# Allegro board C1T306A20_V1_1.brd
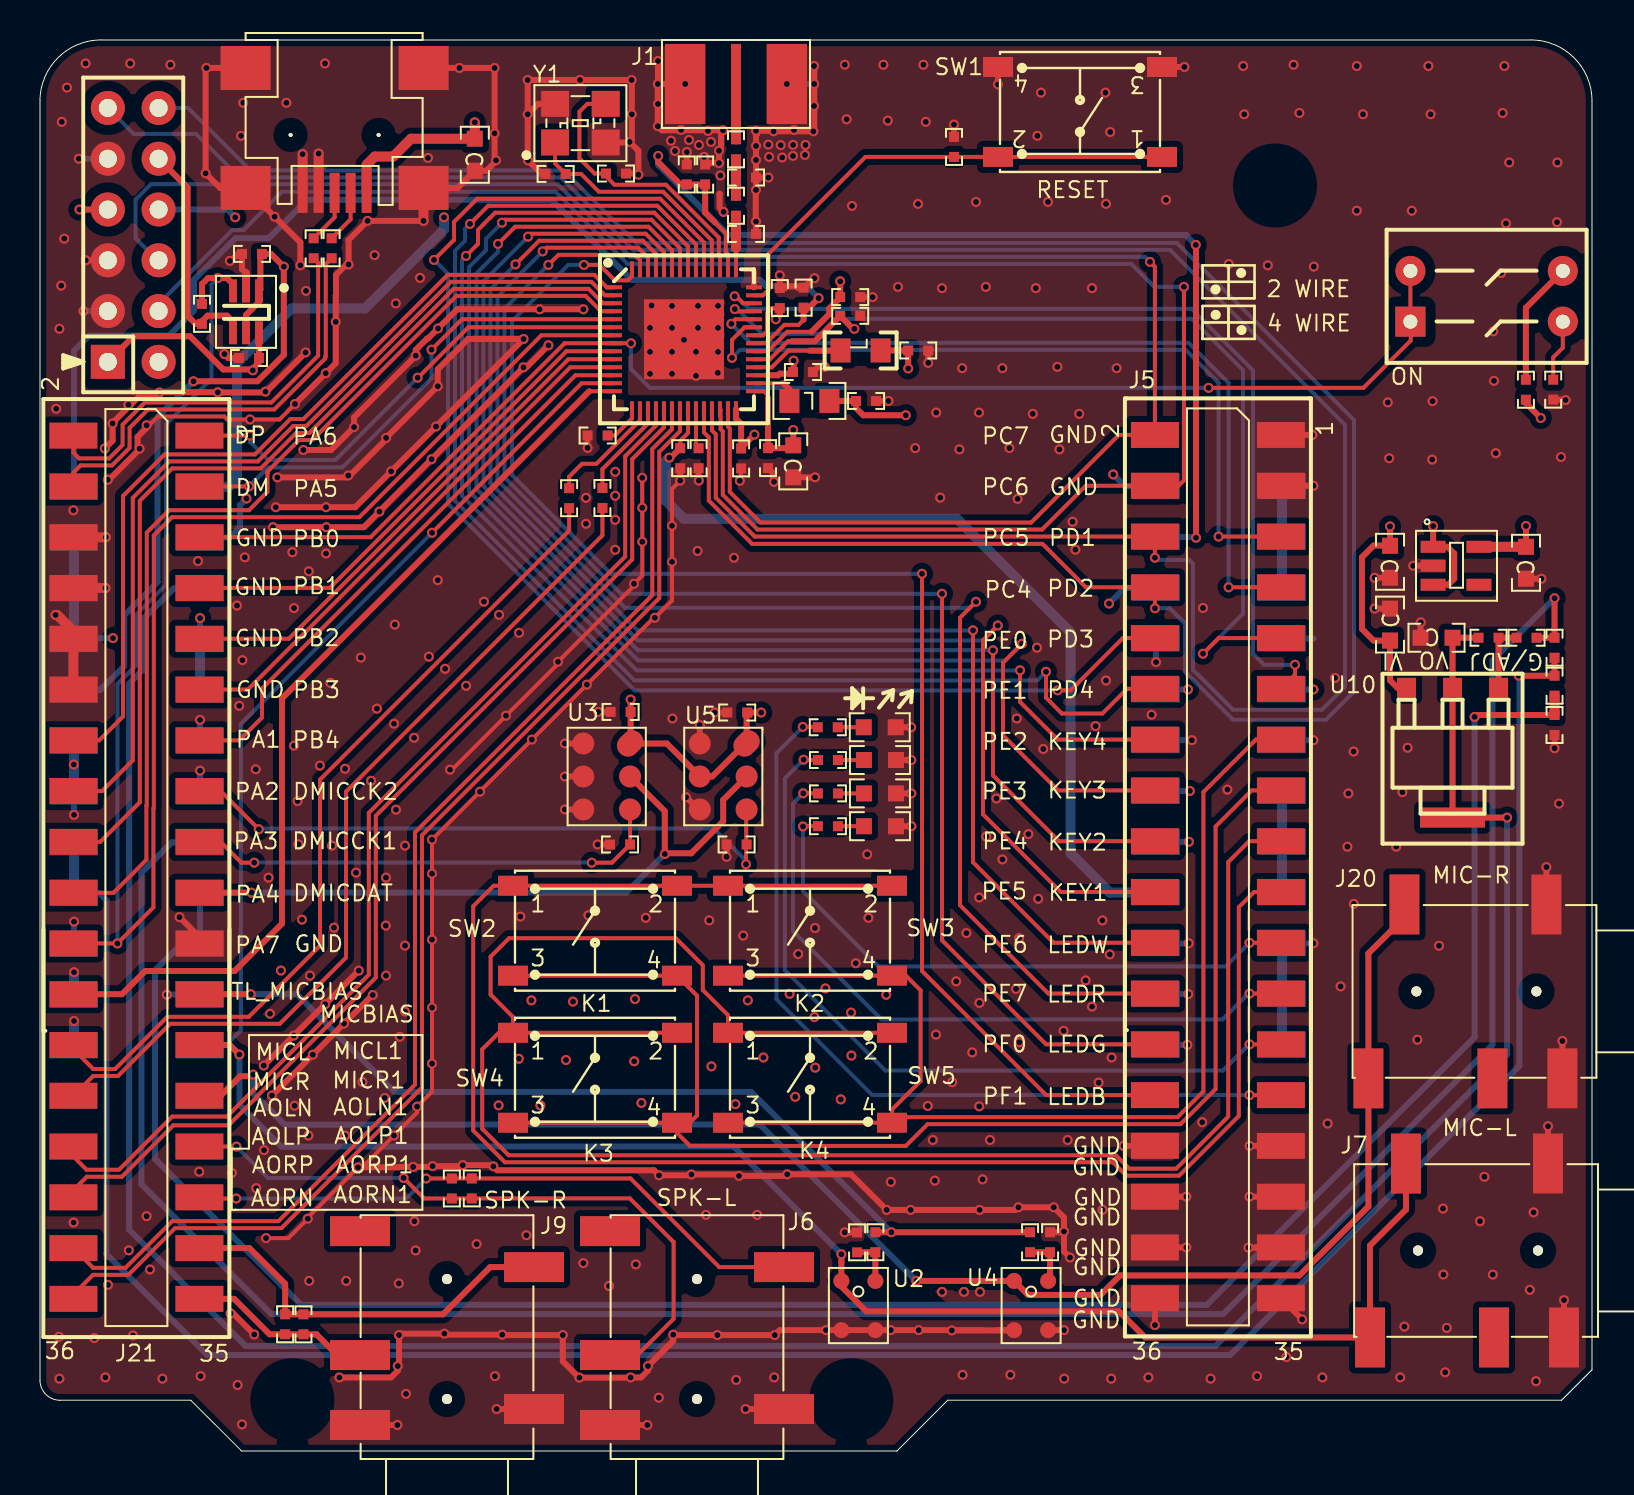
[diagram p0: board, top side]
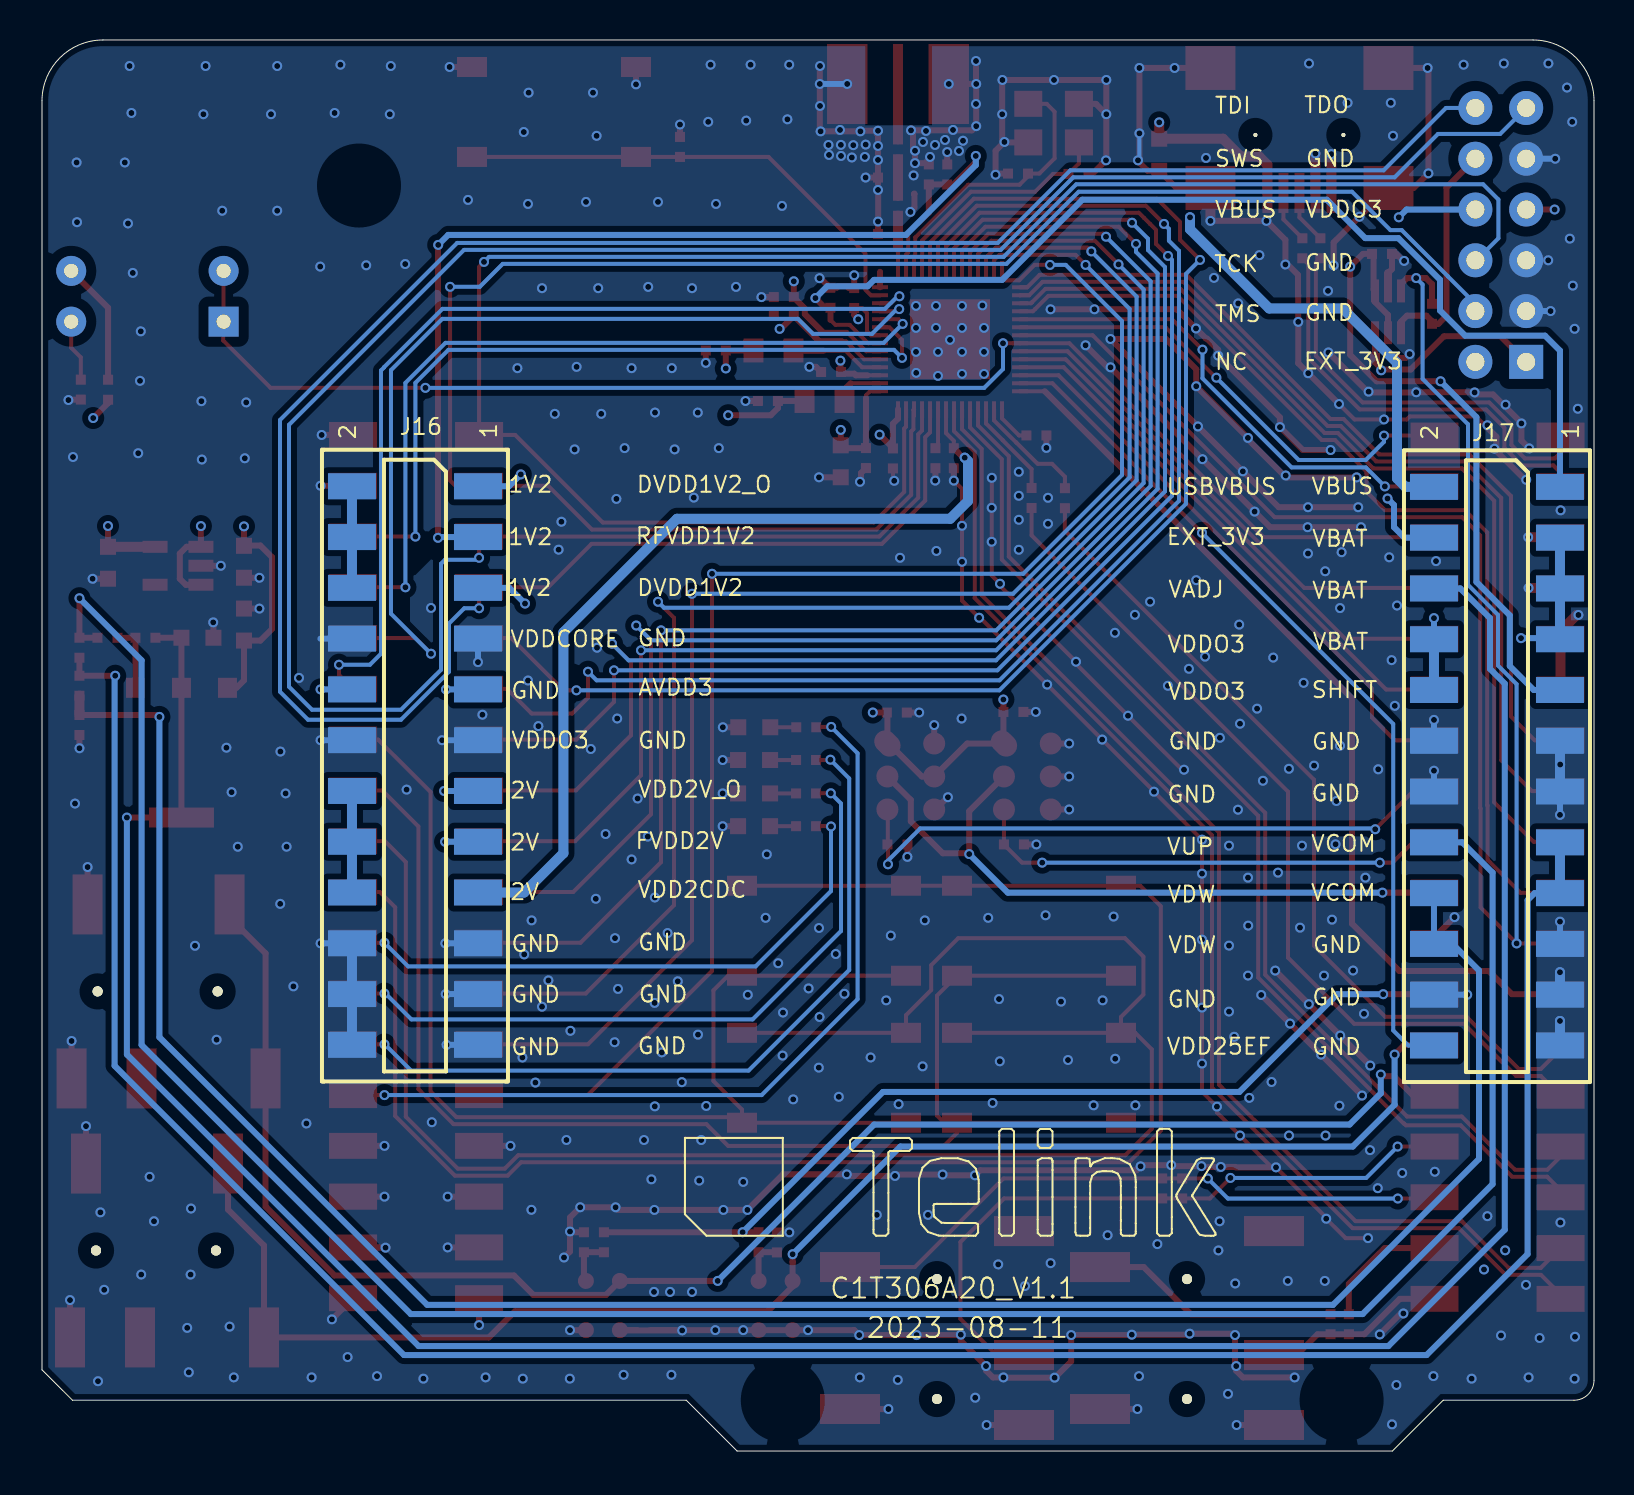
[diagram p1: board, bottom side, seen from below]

Outline 77.6 x 70.58 mm; copper layers: TOP, GND, POWER, BOTTOM. Coordinates in mm from the lower left corner of the outline.
Outline path: 0,67.53 arc(0.89,69.69) 3.05,70.58 74.55,70.58 arc(76.71,69.69) 77.6,67.53 77.6,4.06 76.08,2.54 45.39,2.54 42.85,0 10.08,0 7.54,2.54 1,2.54 arc(0.29,2.83) 0,3.54 0,67.53

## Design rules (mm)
constraint set DEFAULT: min track width 0.15

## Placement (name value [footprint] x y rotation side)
C1  NC  [0402]  28.8 63.9 180 top
C2  NC  [0402]  25.78 63.88 0 top
C3  0.1uF  [0402]  33.26 63.85 90 top
C4  2.2uF  [0402]  32.34 63.85 90 top
C5  1.5pF  [0402]  35.3 60.88 180 top
C6  1.2pF  [0402]  35.3 63.7 180 top
C9  1uF  [0402]  45.7 65.23 90 top
C10  1uF  [0402]  36.99 57.67 90 top
C11  1uF  [0402]  38.18 57.69 90 top
C12  1uF  [0402]  40.51 56.78 0 top
C13  1uF  [0402]  40.51 57.72 0 top
C14  1uF  [0402]  43.91 55.05 0 top
C15  1uF  [0402]  27.88 50.8 0 top
C16  1uF  [0402]  35.06 49.65 270 top
C17  1uF  [0402]  38.15 53.97 0 top
C18  1uF  [0402]  36.4 49.67 270 top
C19  1uF  [0402]  26.46 47.66 90 top
C20  1uF  [0402]  28.12 47.67 90 top
C21  1uF  [0402]  41.3 52.52 0 top
C22  1uF  [0402]  32.01 49.66 270 top
C23  1uF  [0402]  32.93 49.66 270 top
C25  NC  [0402]  21.59 13.13 90 top
C26  1uF  [0402]  40.85 10.44 90 top
C27  0.1uF  [0402]  34.86 36.94 180 top
C28  NC  [0402]  13.17 6.34 90 top
C29  1uF  [0402]  50.5 10.44 90 top
C30  10uF  [0603C]  21.74 64.84 270 top
C31  0.1uF  [0402]  29.03 36.97 180 top
C33  0.1uF  [0402]  10.6 59.88 180 top
C34  0.1uF  [0402]  10.45 54.67 180 top
C37  10uF  [0603C]  67.5 41.34 90 top
C38  10uF  [0603C]  67.5 44.48 270 top
C39  10uF  [0603C]  74.3 44.43 270 top
C40  10uF  [0603C]  69.83 40.68 180 top
C43  10uF  [0603C]  37.66 49.5 270 top
D1  Blue  [0603-LED]  41.99 36.2 0 top
D2  Green  [0603-LED]  42 34.56 0 top
D3  White  [0603-LED]  42 31.25 0 top
D4  Red  [0603-LED]  42 32.89 0 top
J1  RFIN  [SMA-H]  34.8 68.38 270 top
J5  HEADER 18X2  [SMD254M-2X18_RX1_30Y2_40]  58.9 24.15 90 top
J6  AOPHR  [PJ-327]  32.85 -0.4 180 top
J7  AIL1  [PJ-327]  77.9 10.03 270 top
J9  AOPHR  [PJ-327]  20.35 -0.4 180 top
J11  USB_MiniABF  [USB-MINI-F5]  14.73 62.93 180 top
J12  DIP_2X2  [DIPSWITCH_2P54_7P62_2X2]  72.33 57.76 270 top
J15  JTAG  [HDR254F-2X6X850]  3.39 67.18 270 top
J16  HEADER 12X2  [SMD254M-2X12_RX1_30Y2_40]  58.95 34.29 90 bottom
J17  HEADER 12X2  [SMD254M-2X12_RX1_30Y2_40]  4.85 34.26 90 bottom
J20  AIL1  [PJ-327]  77.82 22.99 270 top
J21  HEADER 18X2  [SMD254M-2X18_RX1_30Y2_40]  4.82 24.12 90 top
L1  3nH  [0402]  34.8 62.29 90 top
L2  2.2uH  [0805L]  41.03 55.05 0 top
L3  2.2uH  [0805L]  38.47 52.53 0 top
L4  1.5nH  [0402]  34.8 65.11 90 top
R4  1K  [0402]  39.39 36.2 0 top
R5  1K  [0402]  39.4 34.56 0 top
R6  1K  [0402]  39.4 31.25 0 top
R7  1K  [0402]  39.4 32.89 0 top
R8  NC  [0402]  20.59 13.13 90 top
R9  2.2K  [0402]  41.77 10.44 270 top
R10  100K  [0402]  29 30.34 0 top
R11  NC  [0402]  12.26 6.34 90 top
R12  2.2K  [0402]  49.5 10.44 270 top
R13  100K  [0402]  34.83 30.34 0 top
R14  33  [0402R]  14.58 60.16 270 top
R15  33  [0402R]  13.68 60.16 270 top
R16  1K  [0402]  74.3 53.09 90 top
R17  1M  [0402]  75.66 53.09 90 top
R26  0R  [0402R]  8.1 56.88 270 top
R33  430R  [0402]  74.33 40.68 0 top
R34  1.15K  [0402]  75.73 40.18 270 top
R35  787R  [0402]  75.73 38.28 270 top
R36  464R  [0402]  75.73 36.32 270 top
R37  1K  [0402]  72.43 40.68 180 top
SW1  SW4PIN_4.5x4.5  [SW_6X6_SMD]  52 66.98 180 top
SW2  SW4PIN_4.5x4.5  [SW_6X6_SMD]  27.75 26.03 0 top
SW3  SW4PIN_4.5x4.5  [SW_6X6_SMD]  38.5 26.03 0 top
SW4  SW4PIN_4.5x4.5  [SW_6X6_SMD]  27.75 18.67 0 top
SW5  SW4PIN_4.5x4.5  [SW_6X6_SMD]  38.5 18.67 0 top
U1  TLSR9527C  [QFN_7X7_56PIN_0P4_5P20X5P20]  32.2 55.61 0 top
U2  WMM7037AT2  [GA_BFA423_A83]  40.92 7.28 0 top
U3  WMM7047DTFN0  [DMIC_SPM0423HM4H-WB]  28.33 33.74 270 top
U4  WMM7037AT2  [GA_BFA423_A83]  49.55 7.28 0 top
U5  WMM7047DTFN0  [DMIC_SPM0423HM4H-WB]  34.16 33.74 270 top
U8  NC/TXS0101  [SC70-6]  10.3 56.98 180 top
U10  LM1117-ADJ  [SOT-223]  70.63 34.68 180 top
U11  CE1132-33M  [SOT-23-5]  70.8 44.28 270 top
Y1  24MHz-12pF-+/-10ppm  [OSCCC250X320X110]  27.02 66.42 90 top

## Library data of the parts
C1 C2 = C1005_NC
C3 C4 C9-C18 C21-C23 C26 C27 C29 C31 C38 C39 = C1005X5R1C104K
C5 C6 = C1608_NC
C19 C20 C25 C28 = C1005X5R1C105K
C30 C37 = C1608X5R0J106M
C33 C34 C40 = C1608X5R1C105M
C43 = C1005X5R1C104K_0
D1-D4 = 0603D_Green
J1 = SMA_JACK_2
J5 J21 = HEADER 18X2: Tolerance: RichardLC
J6 J7 J9 J20 = PJ327_2
J11 = USB_MiniABF_5pin: User Part Number: pn; Tolerance: RichardLC
J12 = HEADER 2X2_0: User Part Number: pn; Tolerance: RichardLC
J15 = HEADER 6X2: User Part Number: pn; Tolerance: RichardLC
J16 J17 = HEADER 12X2: Tolerance: RichardLC
L1 L4 = MLK1608_000R
L2 L3 = IND
R4-R7 = RS0402K102JT
R8-R13 R16 R17 = RS0402K104JT
R14 R15 = RS0603K330JT
R26 = RS0603K102JT
R33-R37 = RS0603K104JT
SW1-SW5 = SW_6X6_SMD_0
U1 = TLSR9527C: Tolerance: RichardLC
U2 U4 = MULPS4CX-RM5_0
U3 U5 = LD1117/SO_0
U8 = TXS0101
U10 = XC62FP3302_0.3V_SOT-89
U11 = XC6219_6.3V_SOT-23-5
Y1 = CRYSTAL4/SM_0: Tolerance: RichardLC

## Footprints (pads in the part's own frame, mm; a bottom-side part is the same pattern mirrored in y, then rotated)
0402
  rect 0.5x0.5 smd: 1(-0.5,0) 2(0.5,0)
0402R
  rect 0.5x0.5 smd: 1(-0.5,0) 2(0.5,0)
0603-LED
  rect 0.8x0.8 smd: A(-0.8,0) C(0.8,0)
0603C
  rect 0.8x0.8 smd: 1(-0.8,0) 2(0.8,0)
0805L
  rect 1x1.2 smd: 1(-1,0) 2(1,0)
DIPSWITCH_2P54_7P62_2X2
  rect 1.5x1.5 hole 0.7: 1(1.27,-3.81)
  round 1.5 hole 0.7: 2(1.27,3.81) 3(-1.27,-3.81) 4(-1.27,3.81)
DMIC_SPM0423HM4H-WB
  round 1.1 smd: 1(-1.65,-1.17) 2(0,-1.17) 3(1.65,-1.17) 4(1.65,1.17) 5(0,1.17)
  oval 1.4x1.1 smd rot 135: 6(-1.65,1.17)
GA_BFA423_A83
  round 0.8 smd: 1(-0.85,1.23) 2(-0.85,-1.23) 3(0.85,-1.23) 4(0.85,1.23)
HDR254F-2X6X850
  rect 1.7x1.7 hole 0.9: 1(12.7,0)
  round 1.7 hole 0.9: 2(12.7,2.54) 3(10.16,0) 4(10.16,2.54) 5(7.62,0) 6(7.62,2.54) 7(5.08,0) 8(5.08,2.54) 9(2.54,0) 10(2.54,2.54) 11(0,0) 12(0,2.54)
OSCCC250X320X110
  rect 1.3x1.4 smd: 1(-0.965,1.265) 2(-0.965,-1.265) 3(0.965,-1.265) 4(0.965,1.265)
PJ-327
  round 0.5 hole 1: (0,-3) (0,-9)
  rect 3x1.5 smd: 1(-4.35,-2.5) 2(4.35,-5.2) 3(-4.35,-9.6) 4(4.35,-11.4) 5(4.35,-1.7)
QFN_7X7_56PIN_0P4_5P20X5P20
  rect 0.8x0.2 smd: 1(-3.5,2.6) 2(-3.5,2.2) 3(-3.5,1.8) 4(-3.5,1.4) 5(-3.5,1) 6(-3.5,0.6) 7(-3.5,0.2) 8(-3.5,-0.2) 9(-3.5,-0.6) 10(-3.5,-1) 11(-3.5,-1.4) 12(-3.5,-1.8) 13(-3.5,-2.2) 14(-3.5,-2.6) 29(3.5,-2.6) 30(3.5,-2.2) 31(3.5,-1.8) 32(3.5,-1.4) 33(3.5,-1) 34(3.5,-0.6) 35(3.5,-0.2) 36(3.5,0.2) 37(3.5,0.6) 38(3.5,1) 39(3.5,1.4) 40(3.5,1.8) 41(3.5,2.2) 42(3.5,2.6)
  rect 0.2x0.8 smd: 15(-2.6,-3.5) 16(-2.2,-3.5) 17(-1.8,-3.5) 18(-1.4,-3.5) 19(-1,-3.5) 20(-0.6,-3.5) 21(-0.2,-3.5) 22(0.2,-3.5) 23(0.6,-3.5) 24(1,-3.5) 25(1.4,-3.5) 26(1.8,-3.5) 27(2.2,-3.5) 28(2.6,-3.5) 43(2.6,3.5) 44(2.2,3.5) 45(1.8,3.5) 46(1.4,3.5) 47(1,3.5) 48(0.6,3.5) 49(0.2,3.5) 50(-0.2,3.5) 51(-0.6,3.5) 52(-1,3.5) 53(-1.4,3.5) 54(-1.8,3.5) 55(-2.2,3.5) 56(-2.6,3.5)
  rect 4x4 smd: 57(0,0)
SC70-6
  rect 0.4x1.15 smd: 1(-0.65,-1.045) 2(0,-1.045) 3(0.65,-1.045) 4(0.65,1.045) 5(0,1.045) 6(-0.65,1.045)
SMA-H
  rect 4x0.5 smd: 1(0,0)
  rect 4x2 smd: 2(0,-2.54) 3(0,2.54) 4(0,-2.54) 5(0,2.54)
SMD254M-2X12_RX1_30Y2_40
  rect 1.3x2.4 smd: 1(13.97,-3.15) 2(13.97,3.15) 3(11.43,-3.15) 4(11.43,3.15) 5(8.89,-3.15) 6(8.89,3.15) 7(6.35,-3.15) 8(6.35,3.15) 9(3.81,-3.15) 10(3.81,3.15) 11(1.27,-3.15) 12(1.27,3.15) 13(-1.27,-3.15) 14(-1.27,3.15) 15(-3.81,-3.15) 16(-3.81,3.15) 17(-6.35,-3.15) 18(-6.35,3.15) 19(-8.89,-3.15) 20(-8.89,3.15) 21(-11.43,-3.15) 22(-11.43,3.15) 23(-13.97,-3.15) 24(-13.97,3.15)
SMD254M-2X18_RX1_30Y2_40
  rect 1.3x2.4 smd: 1(26.67,-3.15) 2(26.67,3.15) 3(24.13,-3.15) 4(24.13,3.15) 5(21.59,-3.15) 6(21.59,3.15) 7(19.05,-3.15) 8(19.05,3.15) 9(16.51,-3.15) 10(16.51,3.15) 11(13.97,-3.15) 12(13.97,3.15) 13(11.43,-3.15) 14(11.43,3.15) 15(8.89,-3.15) 16(8.89,3.15) 17(6.35,-3.15) 18(6.35,3.15) 19(3.81,-3.15) 20(3.81,3.15) 21(1.27,-3.15) 22(1.27,3.15) 23(-1.27,-3.15) 24(-1.27,3.15) 25(-3.81,-3.15) 26(-3.81,3.15) 27(-6.35,-3.15) 28(-6.35,3.15) 29(-8.89,-3.15) 30(-8.89,3.15) 31(-11.43,-3.15) 32(-11.43,3.15) 33(-13.97,-3.15) 34(-13.97,3.15) 35(-16.51,-3.15) 36(-16.51,3.15)
SOT-23-5
  rect 0.6x1.25 smd: 1(-0.95,-1.145) 2(0,-1.145) 3(0.95,-1.145) 4(0.95,1.145) 5(-0.95,1.145)
SOT-223
  rect 0.95x1 smd: 1(-2.3,-3.495) 2(0,-3.495) 3(2.3,-3.495)
  rect 3.25x1 smd: 4(0,2.995)
SW_6X6_SMD
  rect 1.5x1 smd: 1(-4.1,2.25) 2(4.1,2.25) 3(-4.1,-2.25) 4(4.1,-2.25)
USB-MINI-F5
  round 0.2 hole 0.9 unplated: (-2.2,-2.9) (2.2,-2.9)
  rect 0.5x2 smd: 1(-1.6,0) 2(-0.8,0) 3(0,0) 4(0.8,0) 5(1.6,0)
  rect 2.5x2.2 smd: 6(-4.45,-6.25) 7(4.45,-6.25) 8(-4.45,-0.25) 9(4.45,-0.25)

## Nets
GND: C1.1 C2.1 C3.2 C4.2 C5.1 C6.1 C9.2 C10.2 C11.2 C12.2 C13.2 C14.2 C15.1 C16.2 C17.2 C18.2 C21.2 C22.2 C23.2 C26.2 C27.2 C29.2 C30.2 C31.2 C33.2 C34.2 C37.2 C38.2 C39.2 C40.2 C43.2 D1.C(CATHODE) D2.C(CATHODE) D3.C(CATHODE) D4.C(CATHODE) J1.2 J1.3 J1.4 J1.5 J5.1 J5.3 J5.29 J5.30 J5.31 J5.32 J5.33 J5.34 J5.35 J5.36 J6.1 J6.5 J7.1 J7.5 J9.1 J9.5 J11.4 J11.5 J11.6 J11.7 J11.8 J11.9 J15.3 J15.5 J15.9 J16.7 J16.8 J16.11 J16.12 J16.19 J16.20 J16.21 J16.22 J16.23 J16.24 J17.11 J17.12 J17.13 J17.14 J17.19 J17.21 J17.22 J17.23 J20.1 J20.5 J21.6 J21.8 J21.10 J21.12 J21.21 R10.1 R13.1 R17.1 R36.2 SW1.3 SW1.4 U1.42 U1.57 U2.2 U2.3 U3.1 U3.2(SE) U3.3 U4.2 U4.3 U5.1 U5.3 U8.2 U11.2(VSS) Y1.2 Y1.4
VBAT_ADJ: C40.1 J17.6 R37.2 U10.2 U10.4(VOUT#4)
VBUS: C30.1 C37.1 C38.1 J11.1(V_BUS) J15.8 J17.2 U10.3 U11.1 U11.3
VDD25_EF: J17.24 U1.13
AOLN: C25.1 J6.2 J21.29 R8.1
AOLP: C25.2 J6.3 J21.31 R8.2
AORN: C28.1 J9.2 J21.35 R11.1
AORP: C28.2 J9.3 J21.33 R11.2
BEVK_SWS: J15.10 R26.2 U8.4
DM: J21.4 R14.2
DMICCK1: J21.17 R10.2 U3.4
DMICCK2: J21.15 R13.2 U5.4
DMICDAT: J21.19 U3.5 U5.5
DP: J21.2 R15.2
EXT_3V3: C34.1 C39.1 J15.1 J17.4 U8.6(VCCB) U11.5
LED_B: J5.27 R4.1
LED_G: J5.25 R5.1
LED_R: J5.23 R7.1
LED_W: J5.21 R6.1
LEVEL_SHIFT: C27.1 C31.1 C33.1 J17.9 U3.6 U5.2(SE) U5.6 U8.1 U8.5
MICBIAS: J21.23 R9.1 R12.1
MICL: J7.3 J7.4 J21.25 U2.1
MICR: J20.3 J20.4 J21.27 U4.1
TL_AOLN: J21.30 U1.18
TL_AOLP: J21.32 U1.19
TL_AORN: J21.36 U1.21
TL_AORP: J21.34 U1.20
TL_AVDD3: C10.1 J16.9 U1.36
TL_DVDD1V2: C17.1 J16.5 U1.31
TL_FVDD2V: C12.1 J16.15 U1.33
TL_KEY1: J5.19 SW2.1 SW2.2 SW3.1 SW3.2
TL_KEY2: J5.17 SW4.1 SW4.2 SW5.1 SW5.2
TL_KEY3: J5.15 SW2.3 SW2.4 SW4.3 SW4.4
TL_KEY4: J5.13 SW3.3 SW3.4 SW5.3 SW5.4
TL_MICBIAS: J21.24 U1.14
TL_MICL: C19.1 J21.26
TL_MICR: C20.1 J21.28
TL_PA1: J21.14 U1.1
TL_PA2: J21.16 U1.2
TL_PA3: J21.18 U1.3
TL_PA4: J21.20 U1.4
TL_PA5_DM: J21.3 U1.5
TL_PA6_DP: J21.1 U1.6
TL_PA7_SWS: J21.22 R26.1 U1.7 U8.3
TL_PB0: J12.1 J12.3 J21.5 U1.8
TL_PB1: J21.7 U1.9
TL_PB2: J21.9 U1.10
TL_PB3: J21.11 U1.11
TL_PB4: J21.13 U1.12
TL_PC4_TDI: J5.8 J15.12 U1.24
TL_PC5_TDO: J5.6 J15.11 U1.25
TL_PC6_TMS: J5.4 J15.4 U1.26
TL_PC7_TCK: J5.2 J15.6 U1.27
TL_PD1: J5.5 U1.37
TL_PD2: J5.7 U1.38
TL_PD3: J5.9 U1.39
TL_PD4: J5.11 U1.40
TL_PE0: J5.10 U1.47
TL_PE1: J5.12 U1.48
TL_PE2: J5.14 U1.49
TL_PE3: J5.16 U1.50
TL_PE4: J5.18 U1.51
TL_PE5: J5.20 U1.52
TL_PE6: J5.22 U1.53
TL_PE7: J5.24 U1.54
TL_PF0: J5.26 U1.55
TL_PF1: J5.28 U1.56
TL_RFVDD1V2: C3.1 C4.1 J16.3 U1.44
TL_RST: C9.1 SW1.1 SW1.2 U1.41
TL_VBAT: C18.1 C43.1 J17.3 J17.5 J17.7 U1.29
TL_VBUS: C11.1 J17.1 U1.35
TL_VDD1V2_O: C21.1 J16.1 L3.2
TL_VDD2CDC: C22.1 J16.17 U1.22
TL_VDD2V_O: C14.1 J16.13 L2.2
TL_VDDO3: C16.1 J15.7 J16.10 J17.8 J17.10 R16.1 U1.28
TL_XC1: C1.2 U1.45 Y1.3
TL_XC2: C2.2 U1.46(XC2) Y1.1
VCOM: J17.15 J17.17 R34.2 R35.1
VDW: J17.18 J17.20 R35.2 R36.1
VUP: J17.16 R33.2 R34.1
N20028206: R33.1 R37.1 U10.1
N20031302: L3.1 U1.30
N20031350: L2.1 U1.32
N20031395: C13.1 U1.34
N20031514: C5.2 L1.1 U1.43
N20031520: C6.2 L1.2 L4.1
N20031898: C23.1 U1.23
N20035363: C26.1 R9.2 U2.4(VDD)
N20035591: C29.1 R12.2 U4.4(VDD)
N20050417: J11.3 R15.1
N20050429: J11.2 R14.1
N20115519: J1.1 L4.2
N20131372: C15.2 U1.15
N20131385: C20.2 U1.17
N20131404: C19.2 U1.16
N20142968: J12.2 R17.2
N20142970: J12.4 R16.2
N20184397: J16.2 J16.4 J16.6
N20184465: J16.14 J16.16 J16.18
N200358921: D4.A R7.2
N200359000: D1.A R4.2
N200359081: D2.A R5.2
N200359160: D3.A R6.2

Pads without a net: J6 4; J7 2; J9 4; J15 2; J20 2; U11 4

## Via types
v1: diameter 0.5, hole 0.3, TOP to BOTTOM, 647 vias

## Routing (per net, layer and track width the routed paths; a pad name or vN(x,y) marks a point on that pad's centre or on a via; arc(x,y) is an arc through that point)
GND: length 451.7
  TOP w0.2: v1(12.75,52.37) 11.98,51.6 v1(10.5,51.6) 9.36,51.6 9.21,51.75 5.9,51.75 5.46,51.31 v1(5.33,51.31) ; v1(30.11,48.68) 30.11,47.18 v1(30.11,47.18) v1(30.11,45.48) 30.11,43.79 v1(29.7,43.38) 29.7,43.28 v1(25.9,39.48) 25.9,39.38 v1(23.3,36.78) 20.6,34.08 v1(20.5,34.08) ; v1(34.99,48.53) 34.99,48.42 35.05,48.48 35.05,49.06 35.1,49.11 C16.2 ; v1(11.3,10.65) 12.42,10.65 v1(13.39,11.62) 13.39,11.68 v1(15.9,14.19) ; v1(32.01,48.54) 31.6,48.13 v1(31.6,46.28) v1(31.6,44.48) 31.6,42.54 v1(30.74,41.68) 30.69,41.68 v1(27.34,38.34) v1(24.59,35.59) 22,32.99 v1(22,32.98) v1(19.6,30.58) 19.7,30.48 19.6,30.38 v1(19.6,28.88) v1(19.6,25.58) v1(19.6,22.18) v1(19.6,19.38) 19.6,17.97 v1(18.85,17.23) 18.85,16.93 v1(17.7,15.78) 16.11,14.19
  TOP w0.3: 45.58,6.05 v1(43.93,6.05) v1(42.54,6.05) U2.3 U2.2 v1(39.3,6.05) 36.99,6.05 v1(36.74,5.8) v1(33.87,5.8) 31.68,5.8 v1(31.66,5.82) 31.66,5.51 v1(30.4,4.25) 30.4,4.03 30.05,3.68 v1(29.53,3.68) 29.52,3.67 v1(26.97,3.67) 26.96,3.67 26.14,4.49 v1(26.14,5.8) 23.13,5.8 v1(23.11,5.82) 20.27,5.82 v1(20.22,5.87) 18.02,5.87 v1(17.95,5.8) 17.95,4.31 v1(17.89,4.25) 17.89,4.02 17.55,3.68 v1(14.97,3.68) ; 45.58,6.05 45.61,6.05 ; 45.58,6.05 v1(45.59,6.03) ; D4.C v1(43.57,32.89) ; 35.8,65.89 v1(35.8,65.28) v1(35.8,64.58) C6.1 ; 35.8,65.89 35.79,65.9 35.86,65.9 35.86,65.9 ; 35.8,65.89 v1(35.8,66.04) 36.65,66.04 v1(36.68,66.01) ; J5.35 v1(63.1,6.59) ; v1(11.19,19.28) v1(12.69,20.78) v1(14.26,22.35) v1(15.94,24.03) ; J5.32 v1(57.32,12.72) ; v1(11.87,48.7) 15.32,48.7 v1(15.42,48.8) 15.5,48.8 17.3,50.6 v1(17.3,50.68) v1(19.89,53.26) 19.89,54.11 21.4,55.62 v1(24.18,55.62) v1(19.8,51.25) v1(17.56,49) 15.76,47.21 v1(14.3,47.21) v1(11.79,47.21) ; J21.21 7.97,25.71 v1(6.97,26.7) ; v1(29.48,65.48) 29.59,65.59 v1(29.59,66.87) 29.59,68.57 v1(29.58,68.58) v1(27,68.58) v1(24.38,68.58) v1(24.38,66.87) ; v1(29.48,65.48) 29.92,65.04 v1(29.92,63.84) 29.83,63.84 29.77,63.9 C1.1 ; v1(29.48,65.48) 29.45,65.45 Y1.2 ; U4.3 v1(51.2,6.05) ; v1(3.39,48.58) 3.45,48.58 4.98,50.11 v1(4.98,50.14) 4.88,50.23 4.88,50.73 5.33,51.18 v1(5.33,51.31) ; C31.2 v1(27.91,36.97) ; C43.2 v1(38.75,48.7) ; J20.1 v1(75.32,29.21) ; v1(24.38,66.87) 24.38,64.68 24.4,64.66 v1(24.4,64.56) 24.58,64.38 24.58,64.38 25.08,63.88 C2.1 ; v1(24.38,66.87) 24.9,67.39 Y1.4 ; v1(69.04,41.45) 69.03,41.44 C40.2 ; C22.2 v1(32.01,48.54) ; v1(51.5,9.68) 51.2,9.98 v1(51.2,10.98) ; v1(16.64,22.81) 16.63,22.81 v1(15.2,21.38) v1(13.64,19.83) v1(11.6,17.78) ; J7.1 v1(75.4,16.25) ; v1(15.9,14.19) 17.93,14.19 17.95,14.21 v1(18.66,14.21) 19.59,14.21 v1(19.63,14.25) 21.09,14.25 v1(21.14,14.3) 22.61,14.3 v1(22.67,14.24) 22.87,14.04 30.7,14.04 v1(30.95,13.79) 32.53,13.79 v1(32.57,13.83) 34.88,13.83 v1(34.95,13.76) 37.28,13.76 v1(37.36,13.84) 40.55,13.84 v1(42.33,12.06) v1(43.53,12.06) v1(46.98,12.06) 48.79,12.06 v1(48.92,12.19) v1(50.69,12.19) 51.2,11.68 v1(51.2,10.98) ; C37.2 v1(66.73,42.14) ; J15.5 v1(2.29,59.56) ; C6.1 v1(36.42,63.7) ; C6.1 v1(35.8,63.08) 35.79,63.07 35.79,61.51 v1(35.8,61.5) C5.1 ; 45.61,6.05 v1(45.59,6.03) ; 45.61,6.05 47.17,6.05 ; v1(45.59,6.03) 48.69,6.03 U4.2 47.83,6.05 ; U11.2 v1(68.66,44.28) ; 33.98,62.9 34,62.88 33.98,62.86 33.98,62.2 34.18,62 v1(34.18,61.98) ; v1(36.68,66.01) 36.55,66.01 ; v1(36.68,66.01) v1(38.67,66.01) 38.71,66.05 v1(38.71,68.38) 38.71,69.27 v1(38.7,69.28) ; U3.3 v1(26.24,32.09) ; J5.1 v1(63.62,50.82) ; C29.2 51.16,10.94 v1(51.2,10.98) ; C26.2 v1(40.23,10.94) ; R36.2 v1(75.73,35.15) ; J5.36 v1(55.75,6.3) ; C18.2 36.65,48.92 36.65,48.53 v1(36.7,48.48) ; C3.2 33.32,64.42 v1(33.95,64.42) v1(33.95,65.04) 34.05,65.14 34.05,65.96 v1(34.15,66.06) 31.1,66.06 v1(30.89,66.27) v1(30.89,68.38) ; J5.34 v1(57.32,10.18) ; C17.2 38.9,54.23 v1(39.23,54.23) ; 10.3,58.92 10.1,59.12 C33.2 9.89,59.88 9.62,59.61 9.61,59.61 9.53,59.53 v1(9.49,59.53) ; v1(27.17,57.11) v1(24.98,57.11) 20.86,57.11 v1(19.9,56.15) 19.39,55.64 19.35,55.64 18.79,55.08 v1(18.79,54.79) 15.7,51.7 v1(15.7,51.22) 14.56,50.07 v1(13.17,50.07) ; J6.5 v1(30.37,1.3) ; J20.5 v1(76.12,20.51) ; J5.3 v1(63.67,48.28) ; v1(30.89,68.38) 30.9,68.39 v1(30.9,69.53) ; v1(30.89,68.38) v1(32.26,68.38) ; C21.2 v1(42.42,52.52) ; J5.30 v1(54.18,15.26) ; D1.C v1(43.56,36.2) ; J5.33 60.78,10.18 60.77,10.17 v1(60.42,10.17) ; R17.1 76.14,52.59 76.16,52.57 v1(76.28,52.57) ; v1(10.71,5.83) 9.66,6.88 v1(9.53,6.88) ; C27.2 v1(33.74,36.94) ; v1(12.75,52.37) v1(14.29,53.91) 14.79,54.41 v1(14.79,56.48) 14.79,57.8 14.8,57.81 14.8,58.83 15.32,59.35 v1(15.43,59.35) 15.43,60.58 v1(16.38,61.53) v1(19.18,61.53) 19.18,61.53 J11.8 20.88,63.18 C30.2 22.32,64.04 22.73,64.45 v1(22.73,65.91) v1(22.73,69.18) v1(20.97,69.18) J11.6 ; U5.1 v1(32.99,36.31) ; C9.2 v1(45.7,66.35) ; U1.42 35.7,58.98 ; U3.2 v1(26.24,33.74) ; v1(13.28,54.95) 11.32,52.99 v1(11.27,52.99) 11.23,52.95 9.1,52.95 9.09,52.96 v1(8.89,52.96) 5.98,52.96 v1(5.97,52.95) 5.87,52.85 5.05,52.85 4.54,52.34 v1(4.42,52.34) 4.42,52.22 3.73,51.53 3.73,51.5 v1(3.63,51.4) 3.63,50.54 v1(3.24,50.15) ; U5.3 32.93,32.09 32.32,32.7 v1(32.3,32.7) ; C13.2 v1(41.63,57.72) ; D2.C v1(43.57,34.56) ; R10.1 v1(27.88,30.34) ; J11.7 v1(8.32,69.18) 8.28,69.14 v1(8.28,63.91) 9.01,63.18 J11.9 11.72,61.74 v1(11.73,61.74) 13.02,60.45 v1(13.02,59.31) ; C39.2 v1(75.07,43.63) ; v1(32.94,48.54) 32.94,48.71 32.93,48.72 C23.2 ; D3.C v1(43.57,31.25) ; J5.29 v1(60.48,15.26) ; J6.1 v1(35.28,2.1) ; SW1.3 v1(57.22,69.23) ; v1(38.72,58.66) 38.67,58.66 38.2,58.19 C11.2 37.87,58.19 37.8,58.26 37.34,58.26 37.25,58.17 C10.2 v1(36.99,58.81) ; U3.1 v1(26.24,35.39) ; C14.2 v1(44.41,54.43) ; SW1.4 v1(47.9,68.36) ; v1(9.22,54.87) 9.42,54.67 C34.2 ; J7.5 v1(76.2,7.55) ; C38.2 v1(66.73,43.68) ; R13.1 v1(34.33,29.72) ; J9.1 v1(22.83,2.1) ; J5.31 v1(60.48,12.72) ; v1(32.34,64.97) 32.34,64.36 C4.2 ; v1(11.65,46.21) v1(14.32,46.21) 16.19,46.21 v1(16.97,46.99) 16.97,47 v1(19.58,49.61) v1(24.17,54.21) 24.32,54.21 v1(25.42,55.31) ; J9.5 v1(17.87,1.3) ; v1(27.38,50.18) C15.1
  TOP w0.4: 10.3,58.92 U8.2
  TOP w0.5: J21.6 v1(3.29,45.71) ; J21.8 v1(3.27,43.17) ; J21.12 J21.10 1.67,41.01 0.86,41.82 v1(0.78,41.82) ; J11.8 19.18,63.18 v1(19.18,61.53) ; J11.5 v1(13.13,64.87) ; J11.4 v1(13.93,64.9)
  BOTTOM w0.2: v1(22.8,64.56) 22.73,64.63 v1(22.73,65.91)
  BOTTOM w0.3: J17.22 v1(6.34,22.83) ; J16.12 v1(63.67,35.56) ; J16.19 v1(57.43,25.4) ; J15.9 v1(1.94,64.64) ; J16.11 v1(57.59,35.56) ; J17.13 v1(1.7,31.82) ; v1(37.34,68.38) v1(38.71,68.38) ; J17.14 v1(8,34.03) ; J16.20 v1(63.67,25.4) ; J17.19 v1(1.7,26.48) ; J16.23 v1(57.37,20.32) ; J16.7 v1(55.8,39.46) ; J15.3 v1(2.17,57.02) ; J17.12 v1(8,36.57) ; J16.8 63.68,40.64 ; J16.21 v1(57.42,22.86)
  BOTTOM w0.5: J17.23 v1(1.7,21.51) ; J16.20 J16.22 J16.24 ; J17.13 J17.11 ; J17.21 v1(1.7,23.95)
  vias: v1(0.81,52.13) v1(0.95,5.71) v1(0.97,56.13) v1(0.97,3.62) v1(1.09,66.48) v1(1.06,58.29) v1(1.21,60.64) v1(1.35,68.2) v1(1.67,47.05) v1(1.69,34.34) v1(1.68,11.43) v1(2.28,69.41) v1(2.72,5.65) v1(3.27,3.68) v1(3.4,8.31) v1(4.44,10.04) v1(4.51,69.41) v1(4.65,5.78) v1(5.33,11.75) v1(5.5,9.08) v1(6.12,3.62) v1(6.52,69.34) v1(7.9,44.51) v1(7.96,13.97) v1(8.03,3.75) v1(9.59,13.91) v1(9.85,42.29) v1(9.88,3.3) v1(9.96,37.27) v1(10.05,65.79) v1(10.12,39.56) v1(10.1,1.33) v1(10.16,67.44) v1(10.24,44.7) v1(10.79,34.1) v1(10.81,13.15) v1(11.2,15.05) v1(11.43,28.68) v1(11.5,21.87) v1(12.05,24.03) v1(12.32,67.44) v1(12.62,44.96) v1(12.7,42.16) v1(12.7,35.28) v1(12.73,17.27) v1(12.88,32.51) v1(12.92,30.35) v1(13.1,26.58) v1(13.3,58.03) v1(13.44,44.01) v1(13.42,15.78) v1(13.5,23.78) v1(13.46,8.51) v1(14,34.28) v1(14.25,69.41) v1(14.3,44.89) v1(14.52,38.42) v1(14.6,30.28) v1(14.7,26.18) v1(15.25,15.78) v1(15.25,34.13) v1(15.31,8.51) v1(15.8,28.93) v1(16.04,39.69) v1(16.12,18.46) v1(16.55,33.53) v1(16.73,59.82) v1(16.85,37.13) v1(17.24,17.66) v1(17.3,28.68) v1(17.29,26.28) v1(17.3,23.78) v1(17.74,41.34) v1(17.7,36.38) v1(17.79,57.4) v1(17.8,32.08) v1(17.94,8.38) v1(17.99,20.72) v1(18.25,30.28) v1(18.25,25.28) v1(18.25,21.98) v1(18.3,2.86) v1(18.7,35.68) v1(18.72,11.49) v1(18.78,10.03) v1(19,58.68) v1(19.4,64.68) v1(19.45,39.73) v1(19.89,43.56) v1(20.25,39.13) v1(21.3,38.28) v1(21.83,10.35) v1(22.2,42.48) v1(22.75,3.75) v1(22.93,17.29) v1(22.95,41.83) v1(23.94,19.62) v1(23.95,40.93) v1(24.02,26.73) v1(24.32,10.8) v1(24.57,22.54) v1(25.02,17.29) v1(26.3,19.56) v1(26.65,22.48) v1(27.17,9.4) v1(27.3,47.68) v1(27.3,46.38) v1(27.42,26.8) v1(28.45,8.25) v1(28.76,48.98) v1(28.76,47.78) v1(28.76,46.58) v1(28.76,45.08) v1(29.71,19.49) v1(29.75,22.61) v1(29.79,9.33) v1(30.07,17.41) v1(30.29,26.67) v1(30.5,56.18) v1(30.5,54.98) v1(30.5,53.88) v1(30.58,57.3) v1(30.9,67.38) v1(30.94,2.67) v1(31.55,65.54) v1(31.6,57.28) v1(31.6,56.18) v1(31.6,54.98) v1(31.6,53.88) v1(31.62,36.64) v1(31.75,65.03) v1(32.05,66.08) v1(32.2,55.58) v1(32.45,65.58) v1(32.8,54.98) v1(32.8,53.78) v1(32.95,65.33) v1(32.9,57.28) v1(32.9,56.18) v1(32.88,45.02) v1(33.2,64.73) v1(33.3,11.81) v1(33.4,66.03) v1(33.55,65.48) v1(33.46,26.54) v1(33.57,19.24) v1(33.9,57.28) v1(33.9,56.18) v1(33.9,54.98) v1(33.89,53.93) v1(34.02,63.8) v1(34.7,44.68) v1(34.77,17.35) v1(34.81,3.56) v1(35.16,25.78) v1(35.39,22.54) v1(35.86,11.81) v1(36.17,19.68) v1(36.42,65.35) v1(36.46,64.73) v1(36.71,3.68) v1(37.04,65.32) v1(37.11,64.7) v1(37.48,22.87) v1(37.65,64.78) v1(37.7,66.08) v1(37.66,65.33) v1(37.76,17.72) v1(37.91,24.86) v1(38.25,64.83) v1(38.28,65.33) v1(38.7,67.28) v1(38.72,21.71) v1(38.75,26.16) v1(38.76,19.18) v1(39.27,23.14) v1(40.04,17.59) v1(40.24,69.34) v1(40.33,66.61) v1(40.55,21.93) v1(40.6,62.28) v1(40.57,19.78) v1(40.79,24.4) v1(41.36,29.84) v1(41.42,26.67) v1(42.17,69.34) v1(42.31,22.82) v1(42.39,66.55) v1(42.54,13.46) v1(42.9,58.23) v1(43.76,50.16) v1(43.9,62.38) v1(44.17,69.34) v1(44.29,66.48) v1(44.39,17.26) v1(44.64,15.56) v1(44.74,13.53) v1(44.81,51.94) v1(44.8,20.83) v1(45.01,47.69) v1(45.1,58.17) v1(45.1,7.96) v1(45.61,18.45) v1(45.81,23.49) v1(45.97,50.1) v1(46.11,54.17) v1(46.13,3.81) v1(46.2,7.96) v1(46.32,25.91) v1(46.61,19.94) v1(46.8,62.48) v1(46.95,51.94) v1(46.96,27.69) v1(46.97,22.42) v1(46.96,17.24) v1(47,7.96) v1(47.13,13.59) v1(47.29,58.23) v1(47.31,30.73) v1(47.5,15.56) v1(47.82,32.64) v1(48.12,54.17) v1(48.12,29.59) v1(48.47,50.16) v1(48.52,3.81) v1(48.84,36.64) v1(48.8,23.11) v1(48.88,47.62) v1(48.95,25.65) v1(48.97,20.45) v1(49.42,30.86) v1(49.64,51.88) v1(49.79,58.17) v1(49.87,65.79) v1(49.85,40.18) v1(49.91,27.62) v1(50.05,67.94) v1(50.16,35.12) v1(50.4,62.48) v1(50.87,54.23) v1(50.97,50.1) v1(51.18,21.02) v1(51.21,3.62) v1(51.38,15.56) v1(51.63,46.48) v1(51.77,45.08) v1(51.96,51.88) v1(52.28,23.54) v1(52.6,58.17) v1(52.6,22.23) v1(52.78,36.26) v1(52.93,18.43) v1(53.12,26.54) v1(53.13,12.06) v1(53.27,67.94) v1(53.3,62.38) v1(53.3,38.54) v1(53.51,65.98) v1(53.49,24.84) v1(53.58,19.68) v1(53.56,3.62) v1(53.83,54.17) v1(55.42,3.68) v1(55.58,36.83) v1(56.3,62.58) v1(58.15,42.17) v1(58.11,16.45) v1(58.53,3.62) v1(59.44,59.37) v1(59.37,33.08) v1(60.16,69.28) v1(60.21,66.87) v1(60.85,3.75) v1(61.39,59.31) v1(62.32,4.7) v1(62.68,69.34) v1(62.97,66.93) v1(63.69,59.25) v1(64.12,3.68) v1(64.38,16.38) v1(64.75,38.67) v1(65.03,23.24) v1(65.42,32.89) v1(65.37,30.23) v1(65.68,34.99) v1(65.69,27.37) v1(65.84,69.28) v1(65.84,62.04) v1(66.15,66.87) v1(67.39,52.45) v1(67.46,49.66) v1(67.81,30.23) v1(68.01,3.68) v1(68.12,32.96) v1(68.22,6.22) v1(68.38,35.18) v1(68.59,62.04) v1(68.87,20.57) v1(69.42,69.28) v1(69.53,66.87) v1(69.63,52.51) v1(69.61,49.59) v1(69.95,25.27) v1(70.15,12.13) v1(70.17,8.83) v1(70.34,6.16) v1(70.26,3.94) v1(72,11.49) v1(72.22,13.72) v1(72.64,8.83) v1(72.66,56.01) v1(72.7,53.53) v1(72.79,49.91) v1(73.13,66.93) v1(73.06,58.93) v1(73.22,69.28) v1(73.3,61.4) v1(73.46,64.45) v1(74.49,8.06) v1(74.68,11.94) v1(74.8,3.49) v1(75.85,61.47) v1(75.87,64.45) v1(76.05,49.72) v1(75.95,32.38)
VBAT_ADJ: length 136.5
  TOP w0.3: R37.2 C40.1 U10.2 70.63,31.68 v1(73.36,31.68)
  BOTTOM w0.3: J17.6 6.69,43.15 5.2,41.66 5.2,39.12 4.46,38.38 4.46,11.07 10.28,5.25 58.77,5.25 73.36,19.84 v1(73.36,31.68)
VBUS: length 49.2
  TOP w0.3: v1(69.66,46.27) U11.1 70.37,45.23 70.71,44.89 70.71,43.63 70.41,43.33 U11.3 ; U10.3 67.88,38.17 67.5,38.55 C37.1 66.68,40.54 66.1,41.12 66.1,44.71 66.68,45.29 67.49,45.29 C38.1 v1(67.5,46.25)
  TOP w0.5: J11.1 16.33,64.34 16.74,64.75 17.66,64.75 18.55,65.64 C30.1 v1(21.74,66.46)
  BOTTOM w0.3: v1(9.76,61.71) 9.37,62.1 J15.8
  BOTTOM w0.5: v1(20.2,61.71) 20.2,61.11 16.24,57.15 12.57,57.15 9.85,54.43 9.85,48.65 9.43,48.23 J17.2
VDD25_EF: length 43.4
  TOP w0.2: v1(19.6,45.93) 27.08,53.41 U1.13
  BOTTOM w0.2: v1(19.6,45.93) 10.04,36.37 10.04,21.04 9.29,20.29 J17.24
AOLN: length 33.5
  TOP w0.2: v1(18.18,13.66) 19.21,12.63 R8.1 20.6,12.63 C25.1 29.5,12.63 31.68,10.45 31.68,6.61 29.87,4.8 J6.2 ; v1(9.82,15.23) J21.29
  BOTTOM w0.2: v1(18.18,13.66) 11.39,13.66 v1(9.82,15.23)
AOLP: length 31.5
  TOP w0.2: J6.3 33.96,9.2 29.53,13.63 C25.2 20.6,13.63 R8.2 v1(19.31,13.63) ; v1(9.81,12.63) 8.03,12.63 J21.31
  BOTTOM w0.2: v1(19.31,13.63) 18.31,12.63 v1(9.81,12.63)
AORN: length 9.2
  TOP w0.3: J21.35 9.71,7.61 11.48,5.84 R11.1 12.26,5.84 C28.1 13.82,5.84 14.86,4.8 J9.2
AORP: length 20
  TOP w0.3: J9.3 22.51,9.2 20.15,6.84 C28.2 12.26,6.84 R11.2 12.26,8.36 10.47,10.15 J21.33
BEVK_SWS: length 11.8
  TOP w0.3: J15.10 7.38,63.19 7.38,56.78 7.78,56.38 R26.2 8.1,56.51 8.38,56.79 9.35,56.79 9.65,56.49 U8.4
DM: length 21.4
  TOP w0.2: R14.2 14.29,59.37 14.29,54.76 14.26,54.73 14.26,54.64 11.72,52.1 5.4,52.1 4.48,51.18 4.48,50.18 3.6,49.3 2.03,49.3 1.67,48.94 J21.4
DMICCK1: length 24.1
  TOP w0.2: v1(10.71,29.43) 10.07,29.43 9.03,30.47 J21.17 ; v1(27.59,29.43) 28.59,29.43 R10.2 U3.4
  BOTTOM w0.2: v1(10.71,29.43) v1(27.59,29.43)
DMICCK2: length 31.8
  TOP w0.2: J21.15 9.03,33.01 v1(10.94,31.1) ; U5.4 35.31,32.07 35.31,30.36 R13.2 35.3,30.31 v1(35.3,29.35)
  BOTTOM w0.2: v1(10.94,31.1) 10.98,31.14 33.69,31.14 35.3,29.53 v1(35.3,29.35)
DMICDAT: length 35
  TOP w0.3: U5.5 34.16,32.57 34.16,31.5 32.56,29.9 31.28,29.9 v1(31.24,29.86) 31.24,32 U3.5 ; J21.19 v1(10.58,27.93)
  BOTTOM w0.3: v1(31.24,29.86) 29.31,27.93 v1(10.58,27.93)
DP: length 20.9
  TOP w0.2: R15.2 13.91,59.44 13.91,54.79 11.57,52.45 5.24,52.45 4.13,51.34 4.13,50.33 3.46,49.65 1.96,49.65 1.67,49.94 J21.2
EXT_3V3: length 17.7
  TOP w0.3: C39.1 v1(74.3,46.27) ; J15.1 4.67,55.76 7.5,55.76 9.16,54.1 10.6,54.1 v1(10.64,54.06) 10.64,54.14 10.95,54.45 C34.1 U8.6
  TOP w0.5: U11.5 C39.1
  BOTTOM w0.3: J17.4 9.48,45.69 10,46.21 10,47.32 v1(10.32,47.64)
LED_B: length 42.1
  TOP w0.2: v1(38.14,36.22) 38.87,36.22 R4.1 ; J5.27 v1(60.48,17.8)
  BOTTOM w0.2: v1(60.48,17.8) 41.62,17.8 36.82,22.6 36.82,34.9 v1(38.14,36.22)
LED_G: length 39.1
  TOP w0.2: R5.1 38.89,34.56 38.2,34.56 v1(38.18,34.58) ; v1(60.48,20.34) 60.58,20.34 60.58,20.34 J5.25
  BOTTOM w0.2: v1(60.48,20.34) 60.46,20.34 59.15,19.03 42.27,19.03 37.24,24.06 37.24,33.64 v1(38.18,34.58)
LED_R: length 34.6
  TOP w0.2: R7.1 38.89,32.9 v1(38.16,32.9) ; v1(60.48,22.88) J5.23
  BOTTOM w0.2: v1(60.48,22.88) 60.42,22.88 59.13,21.59 42.07,21.59 37.65,26.01 37.65,32.39 v1(38.16,32.9)
LED_W: length 29.9
  TOP w0.2: v1(38.15,31.24) 38.17,31.26 38.89,31.26 R6.1 ; v1(60.48,25.42) J5.21
  BOTTOM w0.2: v1(38.15,31.24) 38.15,28.01 41.92,24.24 59.29,24.24 v1(60.48,25.42)
LEVEL_SHIFT: length 45.5
  TOP w0.3: v1(36.06,36.94) C27.1 35.33,36.91 U5.6 35.26,35.39 33.61,33.74 U5.2 31.34,35.39 U3.6 29.53,35.42 C31.1 v1(29.53,37.59) ; v1(7.67,53.51) 10.87,53.51 12.19,54.83 12.19,59.24 ; v1(12.19,59.24) 12.19,59.24 ; 12.19,59.24 11.55,59.88 C33.1 11.02,59.8 11.02,58.09 U8.1 10.95,57.48 10.3,56.83 U8.5
  BOTTOM w0.3: v1(7.67,53.51) 5.88,51.72 5.88,43.47 4.21,41.8 4.21,39.27 3.01,38.07 J17.9
MICBIAS: length 47.3
  TOP w0.3: J21.23 v1(10.54,22.85) ; R9.1 v1(42.57,10.94) R12.1
  BOTTOM w0.3: v1(10.54,22.85) 12.84,22.85 17.73,17.96 35.55,17.96 v1(42.57,10.94)
MICL: length 76.4
  TOP w0.3: v1(9.97,19.83) 9.49,20.31 J21.25 ; v1(40.07,9.84) 40.07,9.46 40.07,9.46 U2.1 40.07,8.23 41.31,6.99 53.95,6.99 55.26,5.68 J7.4 66.5,10.28 68.3,12.08 J7.3
  BOTTOM w0.3: v1(40.07,9.84) 34.68,15.23 12.06,15.23 9.97,17.32 v1(9.97,19.83)
MICR: length 81.7
  TOP w0.3: J20.3 68.22,26.69 66.42,24.89 J20.4 66.42,12.23 62.97,8.78 54,8.78 53.03,7.81 49.4,7.81 U4.1 47.84,8.51 47.84,8.51 v1(43.81,8.51) ; v1(10.66,18.83) 10.58,18.75 10.01,18.75 9.03,17.77 J21.27
  BOTTOM w0.3: v1(10.66,18.83) 10.66,17.89 12.22,16.33 35.99,16.33 v1(43.81,8.51)
TL_AOLN: length 53.8
  TOP w0.2: U1.18 30.8,51.3 29.26,49.76 29.26,44.74 16.44,31.92 16.44,23.82 9.35,16.73 6.61,16.73 3.95,14.07 2.33,14.07 1.67,14.73 J21.30
TL_AOLP: length 54.3
  TOP w0.2: J21.32 1.67,13.05 2.34,13.72 4.09,13.72 6.67,16.29 9.4,16.29 9.49,16.38 9.52,16.38 10.85,17.71 10.85,17.74 16.79,23.68 16.79,31.77 29.61,44.59 29.61,49.61 31.2,51.2 U1.19
TL_AORN: length 61.2
  TOP w0.2: J21.36 1.67,7.83 2.65,8.81 4.42,8.81 6.75,11.15 12.07,11.15 19.1,18.18 19.1,30.8 30.96,42.66 30.96,49.98 32,51.01 U1.21
TL_AORP: length 60.4
  TOP w0.2: J21.34 2.66,9.16 4.27,9.16 6.61,11.5 11.93,11.5 18.75,18.32 18.75,30.95 30.61,42.81 30.61,50.12 31.6,51.11 U1.20
TL_AVDD3: length 4.6
  TOP w0.2: U1.36 36.15,55.81 36.35,56.01 36.35,56.92 36.6,57.17 C10.1
  TOP w0.3: v1(36.79,56.61) 36.85,56.67 36.85,56.68 36.99,56.82 C10.1
  BOTTOM w0.3: J16.9 v1(57.4,38.1)
TL_DVDD1V2: length 5.3
  TOP w0.2: U1.31 36.33,53.81
  TOP w0.3: v1(37.68,54.54) 37.68,54.01 C17.1 37.63,53.97 37.55,53.89 36.99,53.89 36.91,53.81 36.33,53.81
  BOTTOM w0.3: J16.5 54.24,43.18 v1(53.45,42.39)
TL_FVDD2V: length 7.8
  TOP w0.2: U1.33 36.49,54.61 37.13,55.25 37.14,55.25 37.4,55.51 37.6,55.51
  TOP w0.3: 37.6,55.51 38.74,55.51 38.96,55.73 C12.1 40.66,56.13 v1(40.72,56.13)
  BOTTOM w0.3: J16.15 v1(57.45,30.48)
TL_KEY1: length 85.9
  TOP w0.2: SW3.2 SW3.1 SW2.2 SW2.1 22.69,28.28 21.66,27.25 21.66,16.03 23.25,14.44 53.65,14.44 54.32,13.77 56.96,13.77 59.94,16.76 59.94,27.2 60.7,27.96 J5.19
TL_KEY2: length 97
  TOP w0.2: SW4.2 SW4.1 ; SW4.1 23.65,21.71 22.53,22.83 22.53,24.73 23.45,25.65 31.79,25.65 33.14,24.3 33.14,23.06 34.4,21.8 SW5.1 SW5.2 ; SW4.1 22.94,20.92 22.11,20.09 22.11,16.12 23.44,14.79 53.79,14.79 54.46,14.12 56.81,14.12 59.41,16.72 59.41,29.46 60.45,30.5 J5.17
TL_KEY3: length 71
  TOP w0.2: SW4.3 SW4.4 ; SW4.4 32.49,16.42 32.85,16.78 32.85,22.78 SW2.4 SW2.3 ; SW4.4 31.85,15.91 32.5,15.26 43.29,15.26 44.38,16.35 57.02,16.35 58.78,18.1 58.78,31.24 60.58,33.04 J5.15
TL_KEY4: length 61.4
  TOP w0.2: SW5.3 SW5.4 42.6,16.68 ; 42.6,16.68 42.6,17.08 44.03,18.51 44.03,23.04 43.29,23.78 SW3.4 SW3.3 ; 42.6,16.68 42.62,16.7 56.88,16.7 58.17,17.99 58.17,32.96 60.79,35.58 J5.13
TL_MICBIAS: length 46.1
  TOP w0.2: U1.14 27.46,53.01
  TOP w0.3: 27.46,53.01 12.1,37.65 12.1,26.38 9.73,24.01 5.26,24.01 4.1,22.85 J21.24
TL_MICL: length 42.5
  TOP w0.2: J21.26 1.67,20.1 2.66,19.11 3.75,19.11 6.37,21.72 10.44,21.72 14,25.28 14,33.58 26.46,46.04 C19.1
TL_MICR: length 44.3
  TOP w0.2: J21.28 2.66,18.76 3.9,18.76 6.51,21.37 11.99,21.37 15.3,24.68 15.3,32.98 28.12,45.8 C20.1
TL_PA1: length 43.4
  TOP w0.2: U1.1 28.34,58.21 27.72,58.83 20.39,58.83 13.18,51.62 12.52,51.62 10.74,49.85 6.23,49.85 4.15,47.77 4.15,36.74 2.96,35.55 J21.14
TL_PA2: length 45.5
  TOP w0.2: J21.16 3.1,33.01 4.64,34.55 4.64,47.67 6.46,49.5 10.89,49.5 12.66,51.27 13.32,51.27 20.53,58.48 27.57,58.48 28.24,57.81 28.7,57.81 U1.2
TL_PA3: length 47.6
  TOP w0.2: U1.3 28.15,57.41 28.1,57.46 28.1,57.46 27.43,58.13 20.68,58.13 13.46,50.92 12.8,50.92 11.04,49.15 6.61,49.15 4.99,47.53 4.99,32.45 3.01,30.47 J21.18
TL_PA4: length 49.9
  TOP w0.2: J21.20 1.68,27.92 3.67,27.92 5.32,29.57 5.32,32.28 5.34,32.3 5.34,45.94 6.46,47.06 10.45,47.06 11.37,47.98 11.37,48.91 11.37,48.91 11.37,48.99 12.95,50.57 13.61,50.57 20.82,57.78 27.28,57.78 27.95,57.11 27.96,57.11 28.06,57.01 U1.4
TL_PA5_DM: length 25
  TOP w0.2: U1.5 21.1,56.61 v1(19.58,55.09) ; v1(10.46,48.25) J21.3
  BOTTOM w0.2: v1(10.46,48.25) 11.41,49.2 15.12,49.2 19.58,53.66 v1(19.58,55.09)
TL_PA6_DP: length 24.2
  TOP w0.2: v1(10.5,50.79) J21.1 ; v1(18.88,53.69) 18.9,53.69 21.42,56.21 U1.6
  BOTTOM w0.2: v1(18.88,53.69) 14.76,49.57 11.41,49.57 10.5,50.48 v1(10.5,50.79)
TL_PA7_SWS: length 89
  TOP w0.2: U1.7 25.07,55.81 15.97,46.71 6.6,46.71 5.69,45.8 5.69,32.16 5.67,32.14 5.67,27.19 v1(3.87,25.39) J21.22
  TOP w0.3: R26.1 8.1,58.37 8.4,58.67 v1(8.89,58.67) 9.35,58.67 9.65,58.37 U8.3
  BOTTOM w0.2: v1(3.87,25.39) 3.87,38.36 4.8,39.29 4.8,41.83 6.3,43.33 6.3,51.36 8.57,53.63 8.57,58.35 v1(8.89,58.67)
TL_PB0: length 70.7
  TOP w0.2: v1(58.43,53.18) 66.17,53.18 68.54,55.55 68.54,56.47 J12.1 J12.3 ; J21.5 16.53,45.71 26.23,55.41 U1.8 29.55,55.41 v1(29.55,55.41)
  BOTTOM w0.2: v1(29.55,55.41) 29.55,54.12 30.49,53.18 v1(58.43,53.18)
TL_PB1: length 25.6
  TOP w0.2: U1.9 26.32,55.01 14.48,43.17 J21.7
TL_PB2: length 26.5
  TOP w0.2: J21.9 12.44,40.63 26.42,54.61 U1.10
TL_PB3: length 27.4
  TOP w0.2: U1.11 26.51,54.21 10.39,38.09 J21.11
TL_PB4: length 29.1
  TOP w0.2: J21.13 9.96,35.55 11.1,36.69 11.1,38.14 26.77,53.81 U1.12
TL_PC4_TDI: length 123.9
  TOP w0.2: v1(55.75,42.16) J5.8 52.3,43.2 50.12,45.38 35.6,45.38 33.44,47.54 33.44,50.71 33.2,50.95 U1.24
  BOTTOM w0.2: v1(55.75,42.16) 56.48,42.16 57.25,41.39 57.25,38.98 59.65,36.58 64.3,36.58 65.7,37.98 65.7,51.57 56.84,60.43 29.81,60.43 26.18,64.06 10.52,64.06 7.4,67.18 J15.12
TL_PC5_TDO: length 126.1
  TOP w0.2: v1(55.75,44.68) J5.6 35.73,45.74 33.79,47.69 33.79,50.86 33.6,51.05 U1.25
  BOTTOM w0.2: v1(55.75,44.68) 55.85,44.58 57.45,44.58 57.65,44.38 57.65,39.08 59.65,37.08 64.1,37.08 65.25,38.23 65.25,51.33 56.5,60.08 29.66,60.08 26.03,63.71 9.97,63.71 7.8,65.88 4.69,65.88 J15.11
TL_PC6_TMS: length 94.7
  TOP w0.2: v1(57.2,58.23) 57.2,48.55 56.93,48.28 J5.4 52.29,48.28 50.1,46.09 35.88,46.09 34.14,47.83 34.14,51 34.03,51.11 34.03,52.08 U1.26
  BOTTOM w0.2: v1(57.2,58.23) 55.71,58.23 54.56,59.38 29.38,59.38 25.77,62.99 12.1,62.99 10.18,61.07 9.61,61.07 7.3,58.76 7.3,58.75 5.93,57.38 J15.4
TL_PC7_TCK: length 92.8
  TOP w0.2: v1(55.5,59.48) 55.75,59.23 J5.2 53.94,50.82 49.56,46.44 36.02,46.44 34.49,47.97 34.49,51.15 34.4,51.24 U1.27
  BOTTOM w0.2: v1(55.5,59.48) 55.25,59.73 29.52,59.73 25.89,63.36 5.54,63.36 4.78,62.6 4.78,60.66 5.88,59.56 J15.6
TL_PD1: length 38.2
  TOP w0.2: J5.5 58.93,45.74 v1(58.93,45.74) ; U1.37 35.23,56.21 34.6,55.58 v1(34.6,54.68)
  BOTTOM w0.2: v1(58.93,45.74) 58.93,53.43 57.28,55.08 35,55.08 v1(34.6,54.68)
TL_PD2: length 40.2
  TOP w0.2: v1(59.43,43.2) J5.7 ; U1.38 34.77,56.61 34.57,56.41 v1(34.57,56.38)
  BOTTOM w0.2: v1(59.43,43.2) 59.43,53.42 57.42,55.43 35.52,55.43 v1(34.57,56.38)
TL_PD3: length 47.5
  TOP w0.2: v1(58.15,39.88) 58.93,40.66 J5.9 ; v1(34.74,57.12) 34.85,57.01 U1.39
  BOTTOM w0.2: v1(34.74,57.12) 34.86,57.12 36.1,55.88 39.05,55.88 39.8,56.63 57.59,56.63 60.15,54.06 60.15,41.88 v1(58.15,39.88)
TL_PD4: length 46.6
  TOP w0.2: U1.40 35.16,57.41 34.81,57.76 v1(34.73,57.76) ; v1(62.75,39.33) 62.75,38.83 J5.11
  BOTTOM w0.2: v1(62.75,39.33) 61.2,39.33 60.65,39.88 60.65,54.05 60.5,54.2 60.5,54.21 57.58,57.13 35.45,57.13 34.82,57.76 v1(34.73,57.76)
TL_PE0: length 70.3
  TOP w0.2: v1(50.88,38.05) 51.53,38.05 54.14,40.66 J5.10 ; v1(19.7,59.58) 20.7,60.58 20.7,61.48 21.86,62.64 31.01,62.64 33.2,60.45 U1.47
  BOTTOM w0.2: v1(19.7,59.58) 20.4,58.88 20.4,47.38 29.73,38.05 v1(50.88,38.05)
TL_PE1: length 68.9
  TOP w0.2: v1(50.3,38.98) 50.3,37.68 51.09,36.89 53.12,36.89 54.35,38.12 J5.12 ; U1.48 32.8,60.35 30.86,62.29 22.41,62.29 v1(21.5,61.38)
  BOTTOM w0.2: v1(21.5,61.38) 21.25,61.13 21.25,60.54 20.75,60.03 20.75,47.52 29.72,38.55 49.87,38.55 v1(50.3,38.98)
TL_PE2: length 67
  TOP w0.2: v1(21.3,59.78) 21.9,60.38 21.9,61.08 22.2,61.38 22.2,61.39 22.49,61.68 22.5,61.68 22.76,61.94 30.72,61.94 32.4,60.26 U1.49 ; v1(49,39.05) 49,37.47 50.89,35.58 J5.14
  BOTTOM w0.2: v1(49,39.05) 29.83,39.05 21.1,47.78 21.1,59.58 v1(21.3,59.78)
TL_PE3: length 69.9
  TOP w0.2: v1(23.1,61.44) 23.25,61.59 30.57,61.59 32,60.16 U1.50 ; v1(49.1,40.38) 48.15,39.43 48.15,35.8 50.91,33.04 J5.16
  BOTTOM w0.2: v1(23.1,61.44) 22.3,60.64 22.3,60.07 21.45,59.22 21.45,48 29.9,39.55 48.27,39.55 v1(49.1,40.38)
TL_PE4: length 68.1
  TOP w0.2: U1.51 31.6,60.07 30.43,61.24 23.76,61.24 v1(22.9,60.38) ; v1(47.65,40.05) 47.65,33.8 50.95,30.5 J5.18
  BOTTOM w0.2: v1(22.9,60.38) 22.9,59.98 21.82,58.9 21.82,48.12 29.89,40.05 47.65,40.05 v1(47.65,40.05)
TL_PE5: length 70.7
  TOP w0.2: v1(47.89,41.29) 47.15,40.55 47.15,31.85 51.04,27.96 J5.20 ; U1.52 31.2,59.97 30.28,60.89 24.55,60.89 v1(24.4,60.74)
  BOTTOM w0.2: v1(24.4,60.74) 22.17,58.51 22.17,48.27 29.89,40.55 47.15,40.55 v1(47.89,41.29)
TL_PE6: length 69.6
  TOP w0.2: U1.53 30.8,59.88 30.14,60.54 24.96,60.54 v1(23.77,59.35) ; v1(46.65,41.05) 46.65,29.45 50.68,25.42 J5.22
  BOTTOM w0.2: v1(46.65,41.05) 29.89,41.05 22.52,48.41 22.52,58.1 v1(23.77,59.35)
TL_PE7: length 72.3
  TOP w0.2: v1(46.8,42.48) 46,41.68 46,27.3 50.42,22.88 J5.24 ; v1(25.13,60.01) 25.32,60.19 29.91,60.19 30.4,59.7 U1.54
  BOTTOM w0.2: v1(25.13,60.01) 22.87,57.74 22.87,48.56 29.25,42.18 46.5,42.18 v1(46.8,42.48)
TL_PF0: length 71.3
  TOP w0.2: J5.26 50.31,20.34 45.1,25.55 v1(45.1,42.88) ; U1.55 30,59.56 29.73,59.83 25.92,59.83 v1(25.42,59.33)
  BOTTOM w0.2: v1(45.1,42.88) 29.05,42.88 23.22,48.7 23.22,57.13 v1(25.42,59.33)
TL_PF1: length 72.2
  TOP w0.2: J5.28 50.31,17.8 44.1,24.01 v1(44.1,43.88) ; U1.56 29.6,58.76 29.4,58.56 28.74,58.56 27.97,59.33 v1(27.2,59.33)
  BOTTOM w0.2: v1(44.1,43.88) 28.54,43.88 23.6,48.82 23.6,56.52 26.41,59.33 v1(27.2,59.33)
TL_RFVDD1V2: length 53.5
  TOP w0.2: 33.75,61.45 34.29,60.91 34.29,59.96 34.4,59.85 U1.44
  TOP w0.3: v1(57.79,60.33) 57.8,60.32 v1(57.8,45.68) ; v1(30.91,64.78) 30.91,64.47 32.02,63.35 C4.1 C3.1 33.26,61.94 33.75,61.45
  BOTTOM w0.3: J16.3 57.76,45.72 v1(57.8,45.68) ; v1(30.91,64.78) 30.91,64.32 34.4,60.83 57.29,60.83 v1(57.79,60.33)
TL_RST: length 24.3
  TOP w0.2: SW1.1 SW1.2 C9.1 41.27,64.73 36.43,59.89 36.43,58.09 36.15,57.81 U1.41
TL_VBAT: length 12.6
  TOP w0.2: U1.29 36.2,53.01 36.4,52.81 36.4,52.67
  TOP w0.3: 36.4,52.67 36.4,50.89 36.4,50.89 C18.1 37.52,50.17 C43.1 v1(37.66,51.08)
  BOTTOM w0.3: v1(3.65,40.66) 1.86,40.66 1.81,40.61 J17.7
  BOTTOM w0.5: J17.3 J17.5 J17.7
TL_VBUS: length 54.6
  TOP w0.2: 38.18,56.58 37.93,56.33 37.22,56.33 36.29,55.41 U1.35
  TOP w0.3: v1(38.93,57.67) 38.45,57.19 C11.1 38.18,56.58
  BOTTOM w0.3: v1(38.93,57.67) 38.34,58.26 36.32,58.26 36,58.58 29.59,58.58 25.58,62.59 13.36,62.59 11.44,60.67 9.78,60.67 7.7,58.59 7.7,57.05 6.44,55.79 2.45,55.79 1.7,55.04 J17.1
TL_VDD1V2_O: length 6.7
  TOP w0.3: v1(43.29,51.81) 41.16,51.81 40.8,52.17 C21.1 40.8,52.53 L3.2
  BOTTOM w0.3: J16.1 54.25,48.26 v1(53.66,48.85)
TL_VDD2CDC: length 44.2
  TOP w0.2: U1.22 32.4,50.92 32.01,50.53 C22.1
  TOP w0.3: v1(31.46,49.69) 31.54,49.69 C22.1
  BOTTOM w0.5: J16.17 53.49,27.94 51.53,29.9 51.53,40.95 45.85,46.63 32.19,46.63 31.3,47.52 31.3,49.52 v1(31.46,49.69)
TL_VDD2V_O: length 4
  TOP w0.3: v1(43.41,54.15) C14.1 L2.2
  BOTTOM w0.3: J16.13 v1(57.49,33.02)
TL_VDDO3: length 10.8
  TOP w0.3: R16.1 74.3,52.41 v1(75.04,51.67) ; C16.1 35.06,50.18 ; 35.06,50.18 v1(35.72,50.84) ; 35.06,50.18 35.06,51.38 34.8,51.64 U1.28 ; v1(1.97,62.1) J15.7
  BOTTOM w0.3: J16.10 v1(63.67,38.1) ; J17.8 v1(8,41.66)
  BOTTOM w0.5: J17.10 J17.8
TL_XC1: length 14.1
  TOP w0.2: Y1.3 27.36,67.39 26.97,66.99 26.97,64.66 27.73,63.9 C1.2 28.3,63.76 28.72,63.34 31.3,63.34 33.94,60.7 33.94,59.81 34,59.76 U1.45
TL_XC2: length 11.9
  TOP w0.2: U1.46 33.6,59.66 33.59,59.67 33.59,60.55 31.15,62.99 27.94,62.99 27.05,63.88 C2.2 25.75,64.41 Y1.1
VCOM: length 123
  TOP w0.3: R34.2 R35.1 v1(73.94,38.78)
  BOTTOM w0.3: J17.17 2.97,27.91 3.32,27.56 3.32,9.85 8.37,4.8 59.5,4.8 73.97,19.27 73.97,38.75 v1(73.94,38.78)
  BOTTOM w0.5: J17.17 J17.15
VDW: length 110.3
  TOP w0.3: v1(71.73,36.72) 71.83,36.82 R36.1
  TOP w0.5: R35.2 R36.1
  BOTTOM w0.3: v1(71.73,36.72) 71.73,20.7 58.34,7.31 13.05,7.31 5.75,14.61 5.75,24.04 7.08,25.37 J17.20 J17.18
VUP: length 121.5
  TOP w0.3: R33.2 R34.1 v1(75.73,42.66)
  BOTTOM w0.3: J17.16 6.59,30.45 5.07,28.93 5.07,13.35 11.57,6.85 59.16,6.85 72.62,20.31 72.62,39.55 v1(75.73,42.66)
N20028206: length 3.4
  TOP w0.3: R33.1 R37.1 72.93,38.17
N20031302: length 2.5
  TOP w0.2: U1.30 37.17,53.41
  TOP w0.3: L3.1 37.47,53.11 37.17,53.41
N20031350: length 4.7
  TOP w0.2: 38.49,55.04 37.42,55.04 36.59,54.21 U1.32
  TOP w0.3: 38.49,55.04 40.02,55.04 L2.1
N20031395: length 6.4
  TOP w0.2: U1.34 36.39,55.01 37.36,55.98 38.57,55.98
  TOP w0.3: v1(40.01,58.51) C13.1 40.01,57.7 39.46,57.15 39.46,56.87 38.57,55.98
N20031514: length 2.7
  TOP w0.2: 34.8,60.18 34.8,59.11 U1.43
  TOP w0.5: 34.8,60.18 C5.2 L1.1
N20031520: length 1.8
  TOP w0.5: L1.2 C6.2 L4.1
N20031898: length 2
  TOP w0.2: C23.1 32.8,50.29 U1.23
N20035363: length 2.4
  TOP w0.3: C26.1 40.86,9.94 R9.2 U2.4
N20035591: length 2.5
  TOP w0.3: U4.4 50.5,8.61 C29.1 R12.2
N20050417: length 2.7
  TOP w0.2: R15.1 14.73,61.71 J11.3
N20050429: length 2.7
  TOP w0.2: J11.2 15.53,61.61 R14.1
N20115519: length 2.8
  TOP w0.5: J1.1 L4.2
N20131372: length 2
  TOP w0.2: C15.2 28.75,50.8 29.6,51.65 U1.15
N20131385: length 4.9
  TOP w0.2: U1.17 30.4,51.4 29.57,50.57 29.57,50.56 28.12,49.12 C20.2
N20131404: length 5.8
  TOP w0.2: U1.16 30,51.55 28.89,50.45 28.88,50.45 27.82,49.38 27.1,49.38 26.46,48.74 C19.2
N20142968: length 3.1
  TOP w0.2: R17.2 75.66,54.7 76.14,55.19 J12.2
N20142970: length 6.2
  TOP w0.3: R16.2 74.3,57.19 J12.4
N20184397: length 5.1
  BOTTOM w0.5: J16.6 J16.4 J16.2
N20184465: length 5.1
  BOTTOM w0.5: J16.14 J16.16 J16.18
N200358921: length 1.3
  TOP w0.2: R7.2 D4.A
N200359000: length 1.3
  TOP w0.2: R4.2 D1.A
N200359081: length 1.3
  TOP w0.2: R5.2 D2.A
N200359160: length 1.3
  TOP w0.2: R6.2 D3.A

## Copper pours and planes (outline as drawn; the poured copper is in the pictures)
GND on TOP: 36.44,70.27 74.55,70.27 76.49,69.47 77.29,67.53 77.29,4.19 75.95,2.85 45.26,2.85 42.72,0.31 10.21,0.31 7.67,2.85 1,2.85 0.51,3.05 0.31,3.54 0.31,67.53 1.11,69.47 3.05,70.27 33.1,70.27 33.1,66.31 36.44,66.31 ; 34 cut-outs
GND on BOTTOM: 36.44,70.27 74.55,70.27 76.49,69.47 77.29,67.53 77.29,4.19 75.95,2.85 45.26,2.85 42.72,0.31 10.21,0.31 7.67,2.85 1,2.85 0.51,3.05 0.31,3.54 0.31,67.53 1.11,69.47 3.05,70.27 33.1,70.27 33.1,66.31 36.44,66.31 ; 29 cut-outs
GND on GND: 36.44,70.27 74.55,70.27 76.49,69.47 77.29,67.53 77.29,4.19 75.95,2.85 45.26,2.85 42.72,0.31 10.21,0.31 7.67,2.85 1,2.85 0.51,3.05 0.31,3.54 0.31,67.53 1.11,69.47 3.05,70.27 33.1,70.27 33.1,66.31 36.44,66.31
VBUS on POWER: 16.06,66.87 27,66.87 27.11,66.76 27.11,63.71 27.07,63.64 27.06,63.56 27.1,60.78 27.17,60.6 27.35,60.53 70.9,60.58 70.95,47.78 70.91,47.71 70.9,47.62 70.91,47.54 70.95,47.47 70.96,46.81 70.98,41.91 70.99,41.85 71.01,41.8 71.05,37.27 65.97,37.27 65.97,39.25 65.99,39.31 66,39.37 65.99,39.43 65.97,39.49 65.95,57.15 65.88,57.33 65.7,57.4 62.7,57.4 62.69,57.4 39.83,57.37 39.79,57.38 39.75,57.38 34.35,57.38 34.26,57.45 34.15,57.48 34.07,57.47 34,57.43 19.08,57.34 18,57.34 18,60.83 17.93,61.01 17.75,61.08 17.75,61.08 9.59,61.02 9.61,63.44 15.81,63.44 15.99,63.51 16.06,63.69
EXT_3V3 on POWER: outline of 97 points within 0.3,29.08 77.3,70.28 ; 1 cut-out
LEVEL_SHIFT on POWER: 9.72,60.52 17.45,60.58 17.45,57.08 17.52,56.9 17.7,56.83 19.08,56.84 33.9,56.86 33.92,50.22 33.91,48.52 33.93,48.46 33.94,44.26 33.94,44.22 33.96,44.12 34.01,44.04 35.71,42.34 36.88,41.14 36.87,38.33 36.86,38.28 36.85,38.23 36.83,29.27 27.45,29.27 27.45,39.52 27.43,39.61 27.38,39.69 14.07,53 14.07,53.02 14.07,53.07 14.05,53.12 14.06,57.24 14.07,57.29 14.08,57.34 14.07,57.39 14.06,57.45 13.97,57.6 13.81,57.65 9.93,57.65 9.89,57.65 9.86,57.64 9.61,57.89 9.61,60.41
TL_AVDD3 on POWER: 34.45,56.86 39.58,56.87 40.04,55.54 40.14,55.42 40.28,55.38 42.41,55.38 42.46,53.28 42.43,53.22 42.42,53.15 42.43,53.07 42.47,53 42.47,48.61 42.46,48.56 42.45,48.51 42.52,48.34 42.7,48.26 51.56,48.26 52.76,47.07 52.84,47.01 52.93,46.99 60.92,46.99 60.92,43.87 59.31,43.87 59.13,43.8 59.06,43.62 59.06,36.95 56.72,36.95 56.54,36.88 56.47,36.7 56.47,34.41 53.29,34.41 53.11,34.34 53.04,34.16 53.06,32.64 53.06,30.2 53.05,29.37 52.67,28.98 52.64,28.95 43.32,29.01 43.26,29.07 43.23,41.09 56.7,41.03 56.99,41.1 57.06,41.27 57.04,44.39 56.97,44.56 56.79,44.64 45.82,44.65 45.78,44.64 45.75,44.64 45.62,44.64 41.16,48.31 41.13,52.77 41.1,52.88 41.04,52.96 37.94,55.44 37.86,55.48 37.78,55.49 34.45,55.49
TL_DVDD1V2 on POWER: 34.46,54.99 37.69,54.99 40.63,52.65 40.66,48.19 40.68,48.09 40.75,48 45.37,44.19 45.45,44.15 45.53,44.14 56.49,44.14 56.47,41.65 43.08,41.59 42.6,42.12 40.44,44.55 40.4,44.59 39.06,48.4 39.08,48.46 39.05,50.15 39.06,50.83 39.05,50.86 38.94,51.32 38.57,53.2 38.48,53.34 38.32,53.4 35.84,53.4 34.46,53.45
TL_FVDD2V on POWER: 62.8,56.9 65.45,56.9 65.47,39.62 62.42,39.62 62.24,39.55 62.17,39.37 62.17,29.46 58.44,29.46 58.35,29.44 58.27,29.4 53.56,29.4 53.56,30.2 53.57,31.56 60.12,31.56 60.21,31.58 60.29,31.64 60.68,32.02 60.73,32.1 60.75,32.2 60.73,41.72 63.3,41.72 63.48,41.8 63.55,41.97 63.56,55.63 63.49,55.8 63.31,55.88 40.46,55.88 40.11,56.87
TL_VBAT on POWER: 37.08,52.9 38.01,52.9 38.53,50.77 38.5,48.47 38.51,48.43 39.93,44.24 40,44.14 40.1,44.08 42.71,41.24 42.71,29.02 42.72,28.94 42.76,28.87 42.76,28.76 42.83,28.59 43.01,28.52 43.04,28.52 43.04,16.63 3.48,16.63 3.49,29 3.49,30.67 3.49,42.1 4.36,42.1 4.44,42.06 4.53,42.04 4.65,42.06 4.73,42.1 6.82,42.1 6.88,42.04 6.95,41.99 7.08,24.57 7.09,24.38 7.09,24.13 7.16,23.95 7.34,23.88 7.35,23.88 39.9,23.94 40.08,24.02 40.15,24.19 40.15,24.2 40.1,29.07 40.1,41.34 40.09,41.42 40.05,41.49 36.98,45.36 37.01,49.98 37.03,50.98
TL_VDD1V2_O on POWER: 42.97,52.9 53.39,52.9 53.75,52.54 53.75,49.69 53.74,49.64 53.73,49.59 53.75,49.5 53.8,49.42 53.93,49.29 54.01,49.24 54.11,49.22 57.73,49.22 57.73,47.49 53.04,47.49 51.84,48.69 51.76,48.74 51.66,48.76 42.97,48.76
TL_VDD2V_O on POWER: 42.91,55.38 63.06,55.38 63.05,42.22 60.48,42.22 60.3,42.15 60.25,32.3 60.01,32.06 57.9,32.06 53.58,32.12 53.6,33.91 56.75,33.91 56.93,33.99 57,34.16 56.99,34.22 56.97,34.28 56.97,36.45 59.31,36.45 59.49,36.53 59.56,36.7 59.56,43.37 61.1,43.37 61.19,43.39 61.27,43.45 61.35,43.52 61.4,43.6 61.42,43.7 61.42,47.31 61.35,47.48 61.17,47.56 61.08,47.54 61,47.49 58.23,47.49 58.23,49.47 58.16,49.64 57.98,49.72 54.25,49.72 54.25,52.64 54.23,52.74 54.18,52.82 53.67,53.33 53.59,53.38 53.49,53.4 42.95,53.4
TL_VDDO3 on POWER: outline of 121 points within 0.3,0.3 77.3,63.06 ; 1 cut-out

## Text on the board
Ref Des/Silkscreen Bottom: GND | VBAT | SHIFT | VBUS | VCOM | VDDO3 | TDO | EXT_3V3 | TDI | SWS | TMS | NC | TCK | VADJ | VDW | VUP | VDD25EF | USBVBUS | AVDD3 | VDD2V_O | VDD2CDC | DVDD1V2 | DVDD1V2_O | RFVDD1V2 | FVDD2V | VDDCORE | 2V | 1V2 | 2023-08-11 | C1T306A20_V1.1
User.Comments: RESET | IOREF | 3V3 | 5V | TX | RX | # | SCL | AREF | GND | 13 | 12 | 11 | 10 | 9 | 8 | 7 | 6 | 5 | 4 | 3 | 2 | 1 | 0 | SDA | A0 | A5 | VIN | A2 | A1 | A4 | A3 | [#=PWM] | www.arduino.cc | UNO_Rev3.01 | #4 | #5 | #3 | #1 | #2 | TOP | BOTTOM | POWER | ANALOG IN | L | ON | DIGITAL | R10 | R9 | ESD1 | D1 | X1 | E1 | E2 | C3 | C4 | C5 | Cp1 | U2 | ZU4 | C12 | C2 | U1 | R2 | R1 | R3 | R8 | U5' | U5 | C8 | C10 | D2 | F1 | C1 | T1 | R6 | U3 | R14 | R15 | ICSP | R13 | Y2 | R12 | R7 | C11 | C9 | R4 | RESET-EN | R11 | C6 | L1 | X2 | C7 | Y1 | IOL | IOH | GROUND | Xduino
Ref Des/Silkscreen Top: TL_MICBIAS | PA3 | DP | GND | PA2 | PA7 | PA4 | DM | PA1 | AORN | AOLP | AORP | MICR | AOLN | MICL | DMICCK1 | PB2 | PB4 | PB0 | PA6 | PB1 | PB3 | DMICCK2 | DMICDAT | PA5 | MICBIAS | MICR1 | MICL1 | AOLN1 | AORN1 | AOLP1 | AORP1 | SPK-R | K1 | K3 | SPK-L | K2 | K4 | PE5 | PE3 | PE7 | PC7 | PE0 | PE1 | PF0 | PE6 | PE2 | PE4 | PC6 | PC5 | PF1 | PC4 | RESET | LEDR | PD3 | LEDG | LEDB | PD4 | LEDW | PD2 | KEY4 | KEY3 | KEY2 | KEY1 | PD1 | 2 WIRE | 4 WIRE | MIC-R | MIC-L
DISPLAY_TOP: FIGURE | FINISHED_SIZE | 0.3 | 0.7 | 0.9 | 1.0 | DRILL CHART: TOP to BOTTOM | ALL UNITS ARE IN MILLIMETERS | PLATED | NON-PLATED | QTY | 647 | 4 | 12 | 8 | 2
